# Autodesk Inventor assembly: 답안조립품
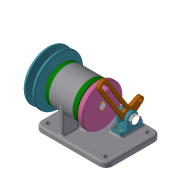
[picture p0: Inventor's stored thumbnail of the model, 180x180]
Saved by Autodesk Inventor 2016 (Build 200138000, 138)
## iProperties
Created: 2019-09
Part Number: 답안조립품
Material: 일반
Document SubType Name: Assembly
Designer: 605-11
Author: 605-11
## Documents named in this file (19)
- C:\Users\605-11\Desktop\390904V1022\답안조립품.iam
- C:\Users\605-11\Desktop\390904V1022\본체.ipt
- C:\Users\605-11\Desktop\390904V1022\베어링 6004.ipt
- C:\Users\605-11\Desktop\390904V1022\볼트 M4.ipt
- C:\Users\605-11\Desktop\390904V1022\오일 실 17 30 5.ipt
- C:\Users\605-11\Desktop\390904V1022\커버.ipt
- C:\Users\605-11\Desktop\390904V1022\V-벨트풀리.ipt
- C:\Users\605-11\Desktop\390904V1022\너트 M10x1.ipt
- C:\Users\605-11\Desktop\390904V1022\축.ipt
- C:\Users\605-11\Desktop\390904V1022\키 4 x 4 x 8.ipt
- C:\Users\605-11\Desktop\390904V1022\키 5 x 5 x 12.ipt
- C:\Users\605-11\Desktop\390904V1022\멈춤나사 M3x5.ipt
- C:\Users\605-11\Desktop\390904V1022\너트 M8.ipt
- C:\Users\605-11\Desktop\390904V1022\와셔 8x15.5.ipt
- C:\Users\605-11\Desktop\390904V1022\크랭크.ipt
- C:\Users\605-11\Desktop\390904V1022\힌지 축.ipt
- C:\Users\605-11\Desktop\390904V1022\힌지.ipt
- C:\Users\605-11\Desktop\390904V1022\핀 3 x 8.ipt
- C:\Users\605-11\Desktop\390904V1022\돌림판.ipt
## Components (3 placed, 2 different names)
1. V-벨트풀리:1
2. 핀 3 x 8:1 — 플러쉬:1
3. 핀 3 x 8:2 — 플러쉬:2
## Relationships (2: Flush 2)
- 플러쉬:1 [Flush]: 핀 3 x 8:1
- 플러쉬:2 [Flush]: 핀 3 x 8:2
